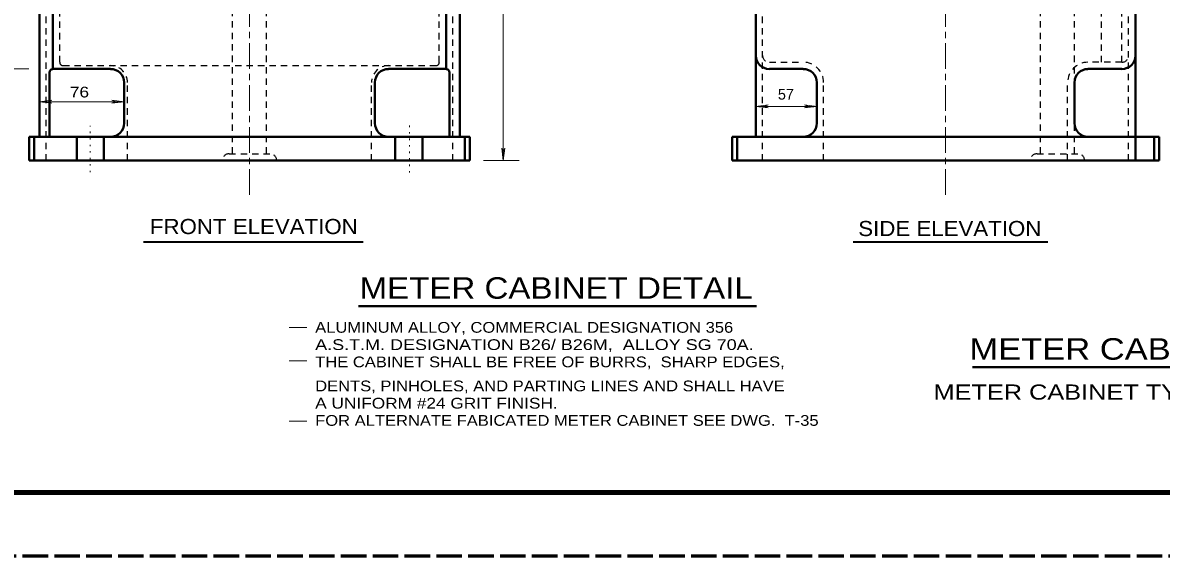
# Model space of a CAD drawing. Extents: x 312583 to 312853, y 144419 to 144586.
# Drawn here: x 312636.2 to 312716.7, y 144418.6 to 144456.3 of the extents above; entities that cross this region are included whole.
import ezdxf
from ezdxf.enums import TextEntityAlignment as Align

# ---------------------------------------------------------------- set-up
doc = ezdxf.new("R2010")
doc.units = 0
doc.header["$LTSCALE"] = 0.3
for name, pattern in [('DOTTED', [1.5, 0.3, -1.2]), ('LONG_DASH_SHORT_DASH', [9.9, 6, -1.2, 1.5, -1.2]), ('LONG_DASHED', [7.5, 6, -1.5]), ('SHORT_DASHED', [2.7, 1.5, -1.2])]:
    doc.linetypes.add(name, pattern=pattern)
for name, color, linetype, lineweight in [('1', 7, 'Continuous', 40), ('2', 7, 'Continuous', 13), ('63', 7, 'LONG_DASHED', 60)]:
    doc.layers.add(name, color=color, linetype=linetype, lineweight=lineweight)

msp = doc.modelspace()

# ---------------------------------------------------------------- linework, layer by layer
at = {"layer": '1', "linetype": 'LONG_DASH_SHORT_DASH', "lineweight": 13}
for p, q in [((312652.2386, 144444.1359), (312652.2386, 144529.7113)), ((312701.4426, 144444.1359), (312701.4426, 144529.7113))]:
    msp.add_line(p, q, dxfattribs=at)
at = {"layer": '1'}
for p, q in [((312637.3883, 144448.2376), (312637.3883, 144523.2253)), ((312667.0966, 144448.2376), (312667.0966, 144523.2253)), ((312714.8593, 144446.5586), (312714.8593, 144523.2483)), ((312638.3466, 144453.0293), (312638.3466, 144523.0029)), ((312666.1383, 144453.0293), (312666.1383, 144523.0029)), ((312638.3466, 144453.0293), (312642.4176, 144453.0293)), ((312666.1383, 144453.0293), (312662.0673, 144453.0293)), ((312688.9843, 144453.0293), (312691.384, 144453.0293)), ((312713.901, 144453.0293), (312711.509, 144453.0293)), ((312638.1089, 144448.2376), (312638.1089, 144452.7916)), ((312666.3759, 144448.2376), (312666.3759, 144452.7916)), ((312643.3759, 144449.1959), (312643.3759, 144452.0709)), ((312661.1089, 144449.1959), (312661.1089, 144452.0709)), ((312692.3423, 144449.1959), (312692.3423, 144452.0709)), ((312710.5506, 144449.1959), (312710.5506, 144452.0709)), ((312636.6676, 144448.2376), (312667.8173, 144448.2376)), ((312636.6676, 144446.5586), (312636.6676, 144448.2376)), ((312637.0279, 144446.5586), (312637.0279, 144448.2376)), ((312640.0256, 144446.5586), (312640.0256, 144448.2376)), ((312641.9423, 144446.5586), (312641.9423, 144448.2376)), ((312662.5426, 144446.5586), (312662.5426, 144448.2376)), ((312664.4593, 144446.5586), (312664.4593, 144448.2376)), ((312667.4569, 144446.5586), (312667.4569, 144448.2376)), ((312667.8173, 144446.5586), (312667.8173, 144448.2376)), ((312686.3546, 144448.2376), (312716.5383, 144448.2376)), ((312686.3546, 144446.5586), (312686.3546, 144448.2376)), ((312686.715, 144446.5586), (312686.715, 144448.2376)), ((312716.178, 144446.5586), (312716.178, 144448.2376)), ((312716.5383, 144446.5586), (312716.5383, 144448.2376)), ((312636.6676, 144446.5586), (312667.8173, 144446.5586)), ((312686.3546, 144446.5586), (312716.5383, 144446.5586))]:
    msp.add_line(p, q, dxfattribs=at)
at = {"layer": '1', "linetype": 'SHORT_DASHED', "lineweight": 25}
for p, q in [((312688.509, 144446.5586), (312688.509, 144523.0336)), ((312637.8636, 144446.5586), (312637.8636, 144522.9876)), ((312638.8219, 144453.5046), (312638.8219, 144523.0183)), ((312665.6553, 144453.5046), (312665.6553, 144523.0183)), ((312666.6136, 144446.5586), (312666.6136, 144522.9876)), ((312712.4673, 144453.5046), (312712.4673, 144487.9739)), ((312713.901, 144453.5046), (312713.901, 144486.7396)), ((312714.384, 144446.5586), (312714.384, 144486.3256)), ((312651.0426, 144447.0416), (312651.0426, 144459.0169)), ((312653.4423, 144447.0416), (312653.4423, 144459.0169)), ((312708.151, 144447.0416), (312708.151, 144459.0169)), ((312710.5506, 144447.0416), (312710.5506, 144459.0169)), ((312639.0673, 144453.2669), (312665.4176, 144453.2669)), ((312688.9843, 144453.5046), (312691.384, 144453.5046)), ((312713.901, 144453.5046), (312711.509, 144453.5046)), ((312643.6136, 144446.5586), (312643.6136, 144452.0709)), ((312660.8636, 144446.5586), (312660.8636, 144452.0709)), ((312692.8176, 144446.5586), (312692.8176, 144452.0709)), ((312710.0676, 144446.5586), (312710.0676, 144452.0709)), ((312650.8049, 144447.0416), (312653.6799, 144447.0416)), ((312707.9133, 144447.0416), (312710.7883, 144447.0416))]:
    msp.add_line(p, q, dxfattribs=at)
at = {"layer": '1', "linetype": 'DOTTED', "lineweight": 13}
for p, q in [((312640.9839, 144445.7383), (312640.9839, 144449.0119)), ((312663.5469, 144445.7076), (312663.5469, 144449.0349))]:
    msp.add_line(p, q, dxfattribs=at)
at = {"layer": '1', "lineweight": 158}
msp.add_line((312616.5, 144423.0846), (312849, 144423.0846), dxfattribs=at)
at = {"layer": '1'}
msp.add_lwpolyline([(312688.026, 144448.2376), (312688.026, 144523.2483), (312701.4426, 144523.4859)], dxfattribs=at)
for centre, radius, start, end in [((312688.9862, 144453.9857), 0.9583, 180, 270), ((312713.9029, 144453.9857), 0.9583, 270, 0), ((312638.3447, 144452.7878), 0.2396, 90, 180), ((312642.4176, 144452.069), 0.9583, 0, 90), ((312662.0634, 144452.069), 0.9583, 90, 180), ((312666.1363, 144452.7878), 0.2396, 0, 90), ((312691.3821, 144452.069), 0.9583, 0, 90), ((312711.5071, 144452.069), 0.9583, 90, 180), ((312642.4176, 144449.194), 0.9583, 270, 0), ((312662.0634, 144449.194), 0.9583, 180, 270), ((312691.3821, 144449.194), 0.9583, 270, 0), ((312711.5071, 144449.194), 0.9583, 180, 270)]:
    msp.add_arc(centre, radius, start, end, dxfattribs=at)
at = {"layer": '1', "linetype": 'SHORT_DASHED', "lineweight": 25}
for centre, radius, start, end in [((312688.9862, 144453.9857), 0.4792, 180, 270), ((312713.9029, 144453.9857), 0.4792, 270, 0), ((312639.0634, 144453.5065), 0.2396, 180, 270), ((312642.4176, 144452.069), 1.1979, 0, 90), ((312662.0634, 144452.069), 1.1979, 90, 180), ((312665.4176, 144453.5065), 0.2396, 270, 0), ((312691.3821, 144452.069), 1.4375, 0, 90), ((312711.5071, 144452.069), 1.4375, 90, 180), ((312650.803, 144446.5586), 0.4792, 90, 180), ((312653.678, 144446.5586), 0.4792, 0, 90), ((312707.9133, 144446.5586), 0.4792, 90, 180), ((312710.7883, 144446.5586), 0.4792, 0, 90)]:
    msp.add_arc(centre, radius, start, end, dxfattribs=at)
at = {"layer": '2'}
for p, q in [((312670.1754, 144446.5586), (312670.1754, 144523.2253)), ((312688.072, 144449.9166), (312688.072, 144454.1409)), ((312636.6293, 144453.0293), (312634.0303, 144453.0293)), ((312637.3883, 144450.7139), (312638.2546, 144450.8213)), ((312637.3883, 144450.7139), (312643.3759, 144450.7139)), ((312637.3883, 144450.7139), (312638.2546, 144450.6066)), ((312638.2546, 144450.8213), (312637.9786, 144450.7139)), ((312638.2546, 144450.6066), (312637.9786, 144450.7139)), ((312642.5096, 144450.8213), (312642.7856, 144450.7139)), ((312643.3759, 144450.7139), (312642.5096, 144450.8213)), ((312642.5096, 144450.6066), (312642.7856, 144450.7139)), ((312643.3759, 144450.7139), (312642.5096, 144450.6066)), ((312688.026, 144450.3843), (312688.8923, 144450.4916)), ((312688.026, 144450.3843), (312692.3423, 144450.3843)), ((312688.026, 144450.3843), (312688.8923, 144450.2769)), ((312688.8923, 144450.4916), (312688.6163, 144450.3843)), ((312688.8923, 144450.2769), (312688.6163, 144450.3843)), ((312691.476, 144450.4916), (312691.752, 144450.3843)), ((312692.3423, 144450.3843), (312691.476, 144450.4916)), ((312691.476, 144450.2769), (312691.752, 144450.3843)), ((312692.3423, 144450.3843), (312691.476, 144450.2769)), ((312670.0681, 144447.4249), (312670.1754, 144447.1489)), ((312670.1754, 144446.5586), (312670.0681, 144447.4249)), ((312670.2827, 144447.4249), (312670.1754, 144447.1489)), ((312670.1754, 144446.5586), (312670.2827, 144447.4249)), ((312668.7756, 144446.5586), (312671.2944, 144446.5586)), ((312655.0336, 144434.7443), (312656.2909, 144434.7443)), ((312655.0336, 144432.3994), (312656.2909, 144432.3994)), ((312655.0336, 144428.144), (312656.2909, 144428.144))]:
    msp.add_line(p, q, dxfattribs=at)
at = {"layer": '2', "lineweight": 35}
for p, q in [((312644.7443, 144440.8163), (312660.2645, 144440.8163)), ((312694.9178, 144440.8163), (312708.6662, 144440.8163))]:
    msp.add_line(p, q, dxfattribs=at)
at = {"layer": '2', "lineweight": 40}
for p, q in [((312659.9454, 144436.2699), (312688.08, 144436.2699)), ((312703.3486, 144431.9613), (312733.5783, 144431.9613))]:
    msp.add_line(p, q, dxfattribs=at)
at = {"layer": '63'}
msp.add_line((312851.75, 144418.5846), (312583.526, 144418.5846), dxfattribs=at)

# ---------------------------------------------------------------- texts
at = {"layer": '2'}
for s, width, p in [('76 ', 1.2, (312639.5397, 144451.0167)), ('ALUMINUM ALLOY, COMMERCIAL DESIGNATION 356', 1.15, (312656.8812, 144434.3829)), ('A.S.T.M. DESIGNATION B26/ B26M,  ALLOY SG 70A.', 1.25, (312656.8812, 144433.1629)), ('THE CABINET SHALL BE FREE OF BURRS,  SHARP EDGES,', 1.15, (312656.8812, 144431.9429)), ('DENTS, PINHOLES, AND PARTING LINES AND SHALL HAVE', 1.15, (312656.8812, 144430.2429)), ('A UNIFORM #24 GRIT FINISH.', 1.2, (312656.8812, 144429.0229)), ('FOR ALTERNATE FABICATED METER CABINET SEE DWG.  T-35', 1.15, (312656.8812, 144427.8029))]:
    msp.add_text(s, height=0.76, dxfattribs=dict(at, width=width)).set_placement(p)
msp.add_text('57', height=0.76, dxfattribs=at).set_placement((312689.5899, 144450.8645))
for s, height, width, p in [('FRONT ELEVATION', 1.07, 1.1, (312652.5436, 144441.3584)), ('SIDE ELEVATION', 1.07, 1.1, (312701.7413, 144441.2166)), ('METER CABINET DETAIL', 1.52, 1.15, (312673.916, 144436.7875)), ('METER CABINET TYPE "T"', 1.52, 1.2, (312718.4948, 144432.4771)), ('METER CABINET TYPE "TL" - SEE NOTE #8', 1.07, 1.25, (312718.9137, 144429.6553))]:
    msp.add_text(s, height=height, dxfattribs=dict(at, width=width)).set_placement(p, align=Align.CENTER)

doc.saveas('drawing.dxf')
